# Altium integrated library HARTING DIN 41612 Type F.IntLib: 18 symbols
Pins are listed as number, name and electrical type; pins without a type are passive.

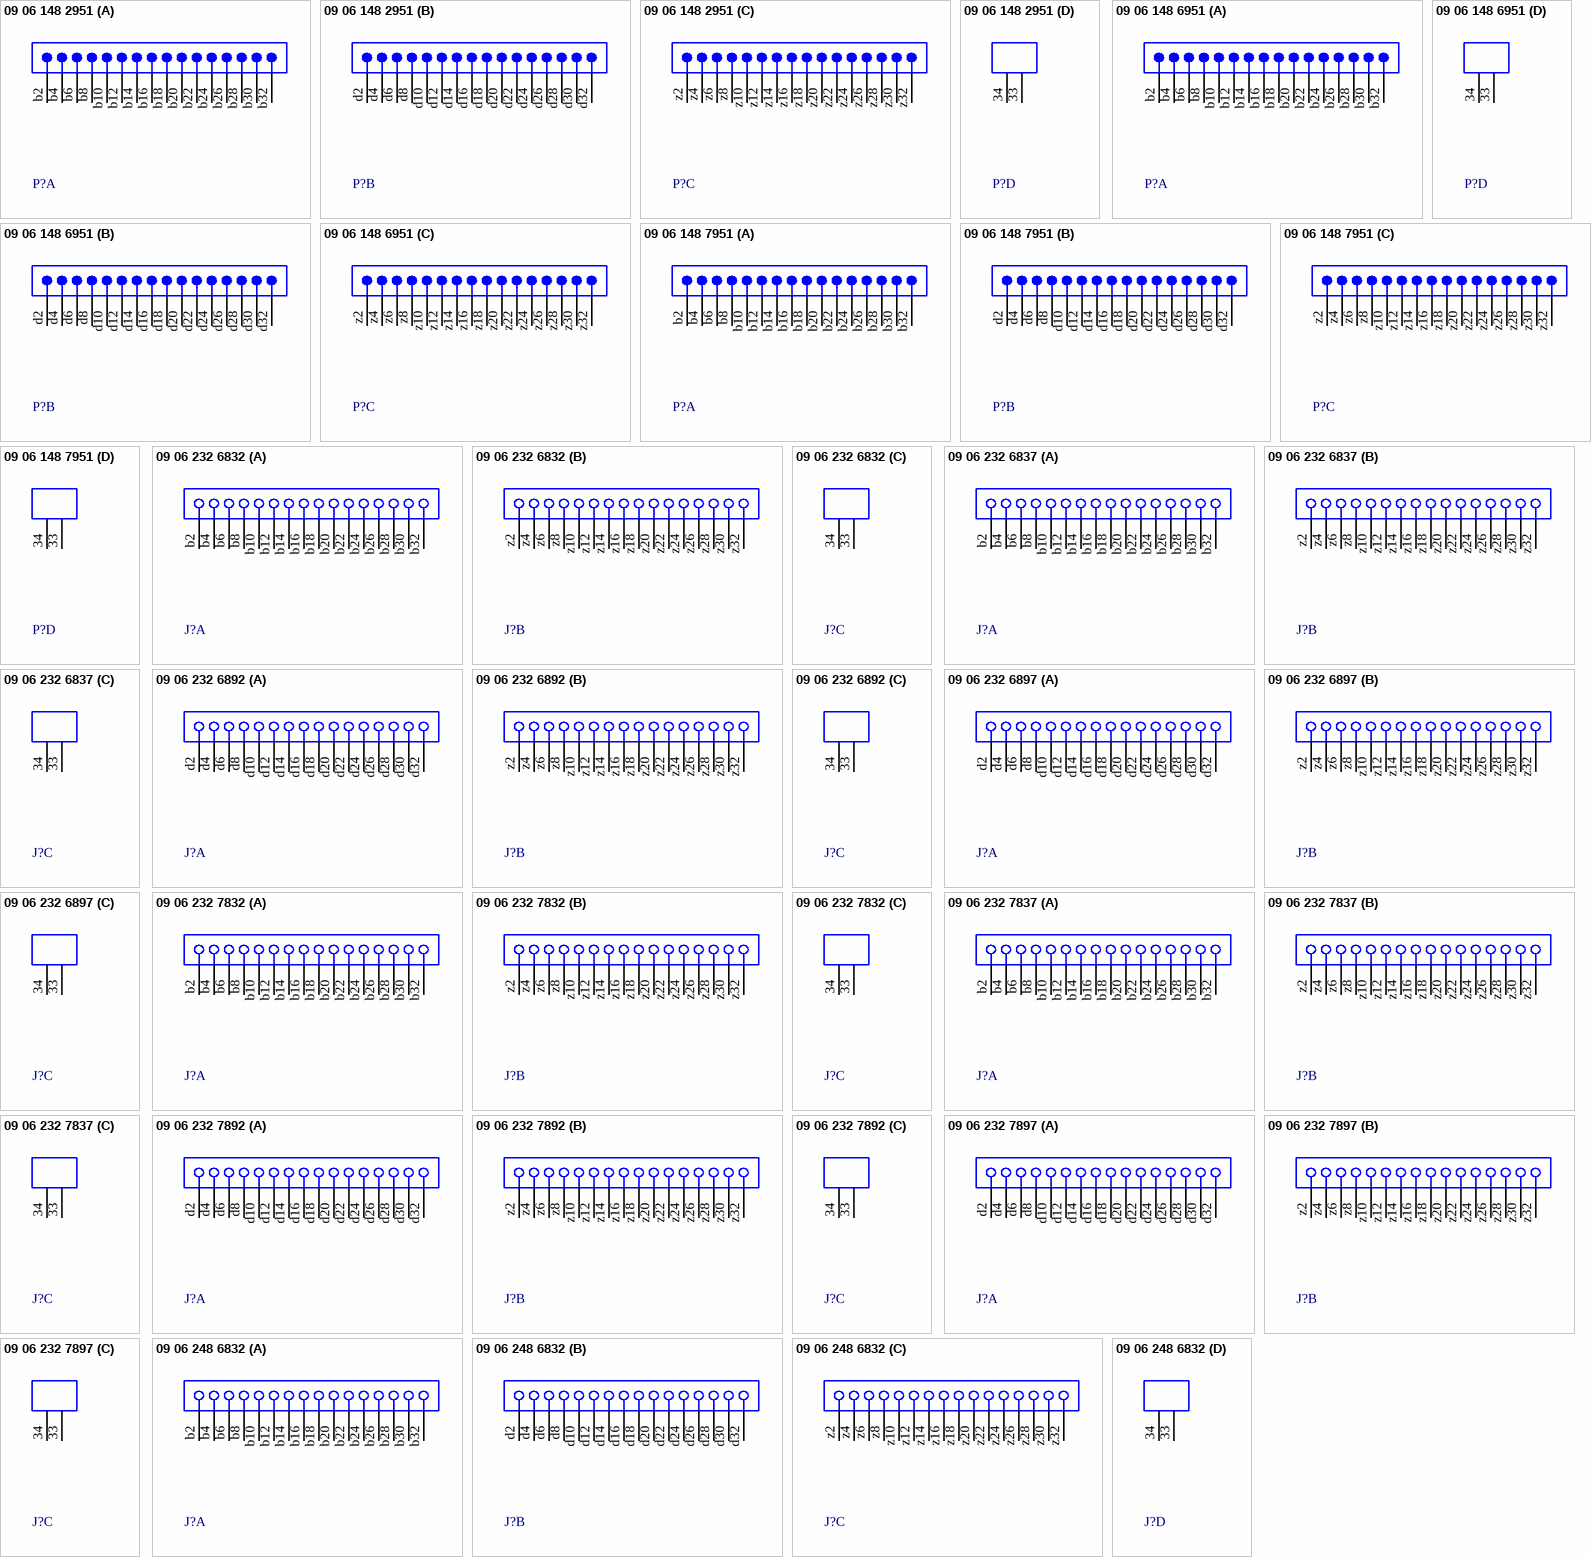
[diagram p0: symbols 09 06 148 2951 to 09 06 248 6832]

## 09 06 148 2951
designator P?
Eurocard DIN 41612, Type F, 48 Position, Rows z+b+d, Performance level 1, Male, Lead 3.0 mm, Pitch 2.54 mm; DrillSize: Corresponds to nominal value.
footprint 0906148x951 (Connector; DIN 41612, Type F, Thru-Hole; Rows z+b+d, 48 Position; Right Angle)
signal-integrity model DIN 41612
part A pins: b2, b4, b6, b8, b10, b12, b14, b16, b18, b20, b22, b24, b26, b28, b30, b32
part B pins: d2, d4, d6, d8, d10, d12, d14, d16, d18, d20, d22, d24, d26, d28, d30, d32
part C pins: z2, z4, z6, z8, z10, z12, z14, z16, z18, z20, z22, z24, z26, z28, z30, z32
part D pins: 33 MH1 "Mounting Fixture", 34 MH2 "Mounting Fixture"

## 09 06 148 6951
designator P?
Eurocard DIN 41612, Type F, 48 Position, Rows z+b+d, Performance level 2, Male, Lead 3.0 mm, Pitch 2.54 mm; DrillSize: Corresponds to nominal value.
footprint 0906148x951 (Connector; DIN 41612, Type F, Thru-Hole; Rows z+b+d, 48 Position; Right Angle)
signal-integrity model DIN 41612
part A pins: b2, b4, b6, b8, b10, b12, b14, b16, b18, b20, b22, b24, b26, b28, b30, b32
part B pins: d2, d4, d6, d8, d10, d12, d14, d16, d18, d20, d22, d24, d26, d28, d30, d32
part C pins: z2, z4, z6, z8, z10, z12, z14, z16, z18, z20, z22, z24, z26, z28, z30, z32
part D pins: 33 MH1 "Mounting Fixture", 34 MH2 "Mounting Fixture"

## 09 06 148 7951
designator P?
Eurocard DIN 41612, Type F, 48 Position, Rows z+b+d, Performance level 3, Male, Lead 3.0 mm, Pitch 2.54 mm; DrillSize: Corresponds to nominal value.
footprint 0906148x951 (Connector; DIN 41612, Type F, Thru-Hole; Rows z+b+d, 48 Position; Right Angle)
signal-integrity model DIN 41612
part A pins: b2, b4, b6, b8, b10, b12, b14, b16, b18, b20, b22, b24, b26, b28, b30, b32
part B pins: d2, d4, d6, d8, d10, d12, d14, d16, d18, d20, d22, d24, d26, d28, d30, d32
part C pins: z2, z4, z6, z8, z10, z12, z14, z16, z18, z20, z22, z24, z26, z28, z30, z32
part D pins: 33 MH1 "Mounting Fixture", 34 MH2 "Mounting Fixture"

## 09 06 232 6832
designator J?
Eurocard DIN 41612, Type F, 32 Position, Rows z+b, Performance level 2, Female, Lead 5.5 mm, Pitch 5.08 mm; DrillSize: Corresponds to nominal value.
footprint 0906232x832 (Connector; DIN 41612, Type F, Thru-Hole; Rows z+b, 32 Position; Vertical)
signal-integrity model DIN 41612
part A pins: b2, b4, b6, b8, b10, b12, b14, b16, b18, b20, b22, b24, b26, b28, b30, b32
part B pins: z2, z4, z6, z8, z10, z12, z14, z16, z18, z20, z22, z24, z26, z28, z30, z32
part C pins: 33 MH1 "Mounting Fixture", 34 MH2 "Mounting Fixture"

## 09 06 232 6837
designator J?
Eurocard DIN 41612, Type F, 32 Position, Rows z+b, Performance level 2, Female, Lead 13.0 mm, Pitch 5.08 mm; DrillSize: Corresponds to nominal value.
footprint 0906232x837 (Connector; DIN 41612, Type F, Thru-Hole; Rows z+b, 32 Position; Vertical)
signal-integrity model DIN 41612
part A pins: b2, b4, b6, b8, b10, b12, b14, b16, b18, b20, b22, b24, b26, b28, b30, b32
part B pins: z2, z4, z6, z8, z10, z12, z14, z16, z18, z20, z22, z24, z26, z28, z30, z32
part C pins: 33 MH1 "Mounting Fixture", 34 MH2 "Mounting Fixture"

## 09 06 232 6892
designator J?
Eurocard DIN 41612, Type F, 32 Position, Rows z+d, Performance level 2, Female, Lead 5.5 mm, Pitch 5.08 mm; DrillSize: Corresponds to nominal value.
footprint 0906232x892 (Connector; DIN 41612, Type F, Thru-Hole; Rows z+d, 32 Position; Vertical)
signal-integrity model DIN 41612
part A pins: d2, d4, d6, d8, d10, d12, d14, d16, d18, d20, d22, d24, d26, d28, d30, d32
part B pins: z2, z4, z6, z8, z10, z12, z14, z16, z18, z20, z22, z24, z26, z28, z30, z32
part C pins: 33 MH1 "Mounting Fixture", 34 MH2 "Mounting Fixture"

## 09 06 232 6897
designator J?
Eurocard DIN 41612, Type F, 32 Position, Rows z+d, Performance level 2, Female, Lead 13.0 mm, Pitch 5.08 mm; DrillSize: Corresponds to nominal value.
footprint 0906232x897 (Connector; DIN 41612, Type F, Thru-Hole; Rows z+d, 32 Position; Vertical)
signal-integrity model DIN 41612
part A pins: d2, d4, d6, d8, d10, d12, d14, d16, d18, d20, d22, d24, d26, d28, d30, d32
part B pins: z2, z4, z6, z8, z10, z12, z14, z16, z18, z20, z22, z24, z26, z28, z30, z32
part C pins: 33 MH1 "Mounting Fixture", 34 MH2 "Mounting Fixture"

## 09 06 232 7832
designator J?
Eurocard DIN 41612, Type F, 32 Position, Rows z+b, Performance level 3, Female, Lead 5.5 mm, Pitch 5.08 mm; DrillSize: Corresponds to nominal value.
footprint 0906232x832 (Connector; DIN 41612, Type F, Thru-Hole; Rows z+b, 32 Position; Vertical)
signal-integrity model DIN 41612
part A pins: b2, b4, b6, b8, b10, b12, b14, b16, b18, b20, b22, b24, b26, b28, b30, b32
part B pins: z2, z4, z6, z8, z10, z12, z14, z16, z18, z20, z22, z24, z26, z28, z30, z32
part C pins: 33 MH1 "Mounting Fixture", 34 MH2 "Mounting Fixture"

## 09 06 232 7837
designator J?
Eurocard DIN 41612, Type F, 32 Position, Rows z+b, Performance level 3, Female, Lead 13.0 mm, Pitch 5.08 mm; DrillSize: Corresponds to nominal value.
footprint 0906232x837 (Connector; DIN 41612, Type F, Thru-Hole; Rows z+b, 32 Position; Vertical)
signal-integrity model DIN 41612
part A pins: b2, b4, b6, b8, b10, b12, b14, b16, b18, b20, b22, b24, b26, b28, b30, b32
part B pins: z2, z4, z6, z8, z10, z12, z14, z16, z18, z20, z22, z24, z26, z28, z30, z32
part C pins: 33 MH1 "Mounting Fixture", 34 MH2 "Mounting Fixture"

## 09 06 232 7892
designator J?
Eurocard DIN 41612, Type F, 32 Position, Rows z+d, Performance level 3, Female, Lead 5.5 mm, Pitch 5.08 mm; DrillSize: Corresponds to nominal value.
footprint 0906232x892 (Connector; DIN 41612, Type F, Thru-Hole; Rows z+d, 32 Position; Vertical)
signal-integrity model DIN 41612
part A pins: d2, d4, d6, d8, d10, d12, d14, d16, d18, d20, d22, d24, d26, d28, d30, d32
part B pins: z2, z4, z6, z8, z10, z12, z14, z16, z18, z20, z22, z24, z26, z28, z30, z32
part C pins: 33 MH1 "Mounting Fixture", 34 MH2 "Mounting Fixture"

## 09 06 232 7897
designator J?
Eurocard DIN 41612, Type F, 32 Position, Rows z+d, Performance level 3, Female, Lead 13.0 mm, Pitch 5.08 mm; DrillSize: Corresponds to nominal value.
footprint 0906232x897 (Connector; DIN 41612, Type F, Thru-Hole; Rows z+d, 32 Position; Vertical)
signal-integrity model DIN 41612
part A pins: d2, d4, d6, d8, d10, d12, d14, d16, d18, d20, d22, d24, d26, d28, d30, d32
part B pins: z2, z4, z6, z8, z10, z12, z14, z16, z18, z20, z22, z24, z26, z28, z30, z32
part C pins: 33 MH1 "Mounting Fixture", 34 MH2 "Mounting Fixture"

## 09 06 248 6832
designator J?
Eurocard DIN 41612, Type F, 48 Position, Rows z+b+d, Performance level 2, Female, Lead 5.5 mm, Pitch 5.08 mm; DrillSize: Corresponds to nominal value.
footprint 0906248x832 (Connector; DIN 41612, Type F, Thru-Hole; Rows z+b+d, 48 Position; Vertical)
signal-integrity model DIN 41612
part A pins: b2, b4, b6, b8, b10, b12, b14, b16, b18, b20, b22, b24, b26, b28, b30, b32
part B pins: d2, d4, d6, d8, d10, d12, d14, d16, d18, d20, d22, d24, d26, d28, d30, d32
part C pins: z2, z4, z6, z8, z10, z12, z14, z16, z18, z20, z22, z24, z26, z28, z30, z32
part D pins: 33 MH1 "Mounting Fixture", 34 MH2 "Mounting Fixture"

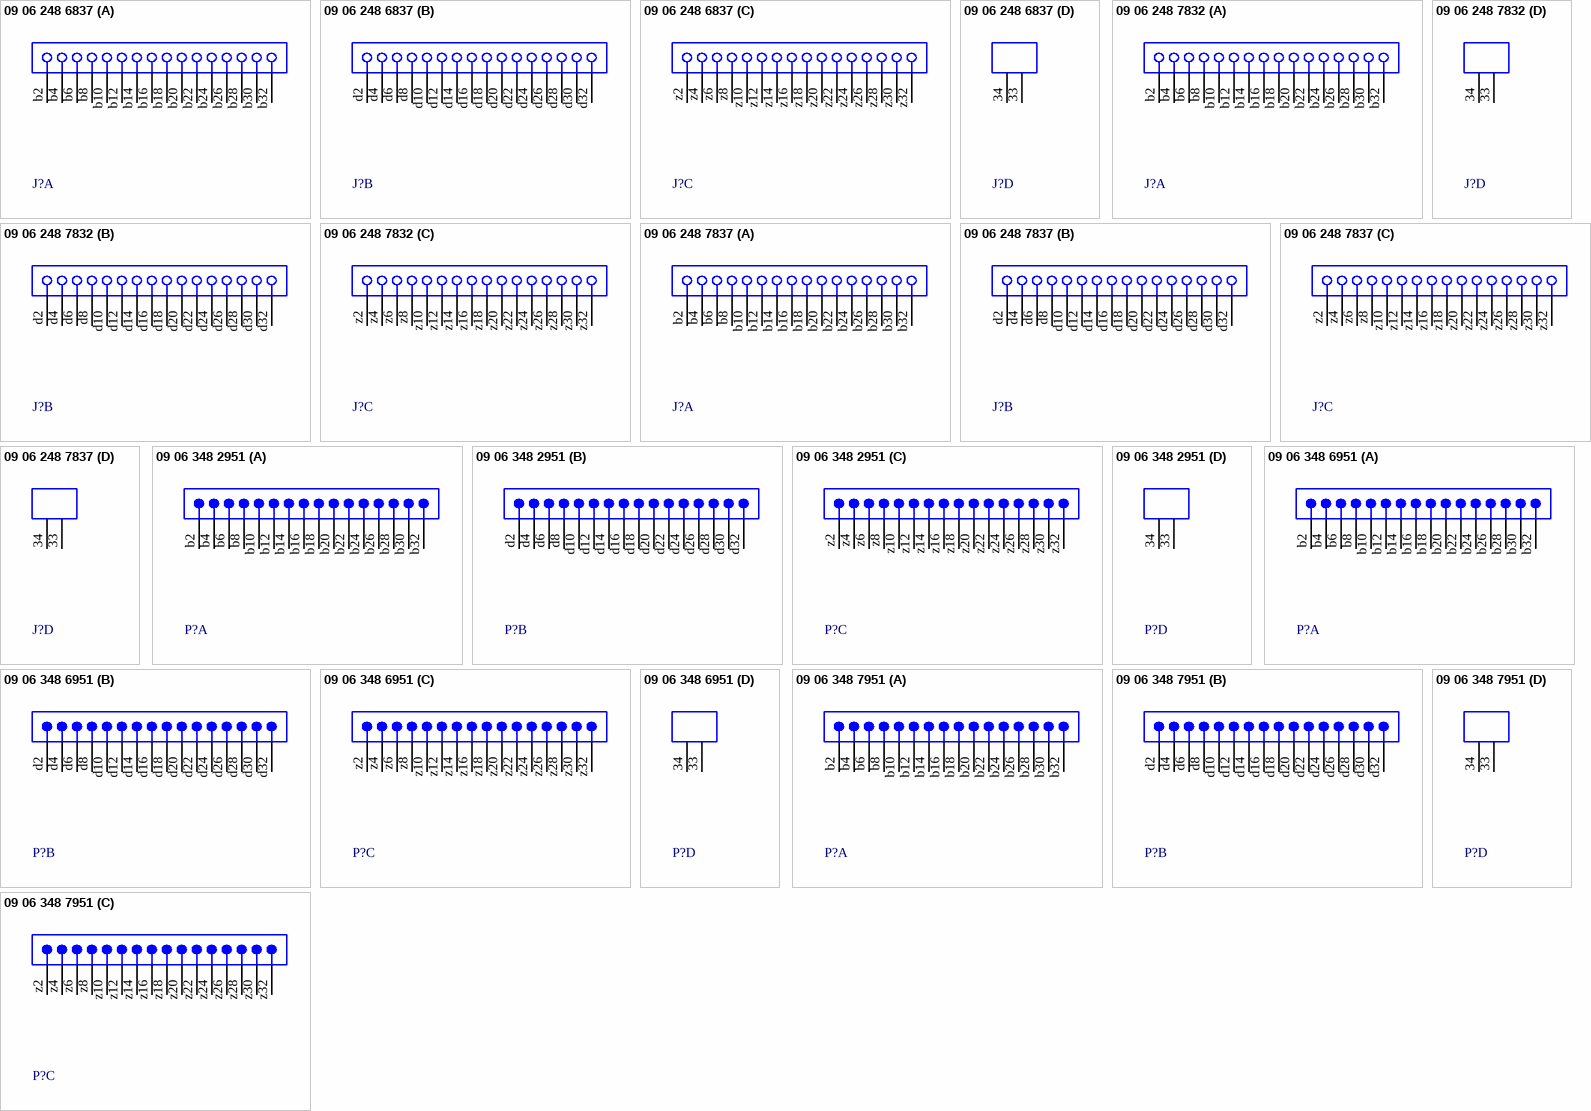
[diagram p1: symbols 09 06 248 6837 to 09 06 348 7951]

## 09 06 248 6837
designator J?
Eurocard DIN 41612, Type F, 48 Position, Rows z+b+d, Performance level 2, Female, Lead 13.0 mm, Pitch 5.08 mm; DrillSize: Corresponds to nominal value.
footprint 0906248x837 (Connector; DIN 41612, Type F, Thru-Hole; Rows z+b+d, 48 Position; Vertical)
signal-integrity model DIN 41612
part A pins: b2, b4, b6, b8, b10, b12, b14, b16, b18, b20, b22, b24, b26, b28, b30, b32
part B pins: d2, d4, d6, d8, d10, d12, d14, d16, d18, d20, d22, d24, d26, d28, d30, d32
part C pins: z2, z4, z6, z8, z10, z12, z14, z16, z18, z20, z22, z24, z26, z28, z30, z32
part D pins: 33 MH1 "Mounting Fixture", 34 MH2 "Mounting Fixture"

## 09 06 248 7832
designator J?
Eurocard DIN 41612, Type F, 48 Position, Rows z+b+d, Performance level 3, Female, Lead 5.5 mm, Pitch 5.08 mm; DrillSize: Corresponds to nominal value.
footprint 0906248x832 (Connector; DIN 41612, Type F, Thru-Hole; Rows z+b+d, 48 Position; Vertical)
signal-integrity model DIN 41612
part A pins: b2, b4, b6, b8, b10, b12, b14, b16, b18, b20, b22, b24, b26, b28, b30, b32
part B pins: d2, d4, d6, d8, d10, d12, d14, d16, d18, d20, d22, d24, d26, d28, d30, d32
part C pins: z2, z4, z6, z8, z10, z12, z14, z16, z18, z20, z22, z24, z26, z28, z30, z32
part D pins: 33 MH1 "Mounting Fixture", 34 MH2 "Mounting Fixture"

## 09 06 248 7837
designator J?
Eurocard DIN 41612, Type F, 48 Position, Rows z+b+d, Performance level 3, Female, Lead 13.0 mm, Pitch 5.08 mm; DrillSize: Corresponds to nominal value.
footprint 0906248x837 (Connector; DIN 41612, Type F, Thru-Hole; Rows z+b+d, 48 Position; Vertical)
signal-integrity model DIN 41612
part A pins: b2, b4, b6, b8, b10, b12, b14, b16, b18, b20, b22, b24, b26, b28, b30, b32
part B pins: d2, d4, d6, d8, d10, d12, d14, d16, d18, d20, d22, d24, d26, d28, d30, d32
part C pins: z2, z4, z6, z8, z10, z12, z14, z16, z18, z20, z22, z24, z26, z28, z30, z32
part D pins: 33 MH1 "Mounting Fixture", 34 MH2 "Mounting Fixture"

## 09 06 348 2951
designator P?
Eurocard DIN 41612, Type F, 48 Position, Rows z+b+d, Performance level 1, Male, Lead 3.0 mm, Pitch 2.54 mm; DrillSize: Corresponds to nominal value.
footprint 0906348x951 (Connector; DIN 41612, Type F, Thru-Hole; Rows z+b+d, 48 Position; Right Angle)
signal-integrity model DIN 41612
part A pins: b2, b4, b6, b8, b10, b12, b14, b16, b18, b20, b22, b24, b26, b28, b30, b32
part B pins: d2, d4, d6, d8, d10, d12, d14, d16, d18, d20, d22, d24, d26, d28, d30, d32
part C pins: z2, z4, z6, z8, z10, z12, z14, z16, z18, z20, z22, z24, z26, z28, z30, z32
part D pins: 33 MH1 "Mounting Fixture", 34 MH2 "Mounting Fixture"

## 09 06 348 6951
designator P?
Eurocard DIN 41612, Type F, 48 Position, Rows z+b+d, Performance level 2, Male, Lead 3.0 mm, Pitch 2.54 mm; DrillSize: Corresponds to nominal value.
footprint 0906348x951 (Connector; DIN 41612, Type F, Thru-Hole; Rows z+b+d, 48 Position; Right Angle)
signal-integrity model DIN 41612
part A pins: b2, b4, b6, b8, b10, b12, b14, b16, b18, b20, b22, b24, b26, b28, b30, b32
part B pins: d2, d4, d6, d8, d10, d12, d14, d16, d18, d20, d22, d24, d26, d28, d30, d32
part C pins: z2, z4, z6, z8, z10, z12, z14, z16, z18, z20, z22, z24, z26, z28, z30, z32
part D pins: 33 MH1 "Mounting Fixture", 34 MH2 "Mounting Fixture"

## 09 06 348 7951
designator P?
Eurocard DIN 41612, Type F, 48 Position, Rows z+b+d, Performance level 3, Male, Lead 3.0 mm, Pitch 2.54 mm; DrillSize: Corresponds to nominal value.
footprint 0906348x951 (Connector; DIN 41612, Type F, Thru-Hole; Rows z+b+d, 48 Position; Right Angle)
signal-integrity model DIN 41612
part A pins: b2, b4, b6, b8, b10, b12, b14, b16, b18, b20, b22, b24, b26, b28, b30, b32
part B pins: d2, d4, d6, d8, d10, d12, d14, d16, d18, d20, d22, d24, d26, d28, d30, d32
part C pins: z2, z4, z6, z8, z10, z12, z14, z16, z18, z20, z22, z24, z26, z28, z30, z32
part D pins: 33 MH1 "Mounting Fixture", 34 MH2 "Mounting Fixture"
